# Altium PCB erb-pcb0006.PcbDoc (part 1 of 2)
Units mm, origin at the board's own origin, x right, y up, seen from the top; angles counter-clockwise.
Board outline 100 x 66.5 mm, 4 copper layers (Top Layer, Mid-Layer 1, Mid-Layer 2, Bottom Layer), stack 1.564 mm thick; 134 components, 81 nets, 741 pads, 81 vias.
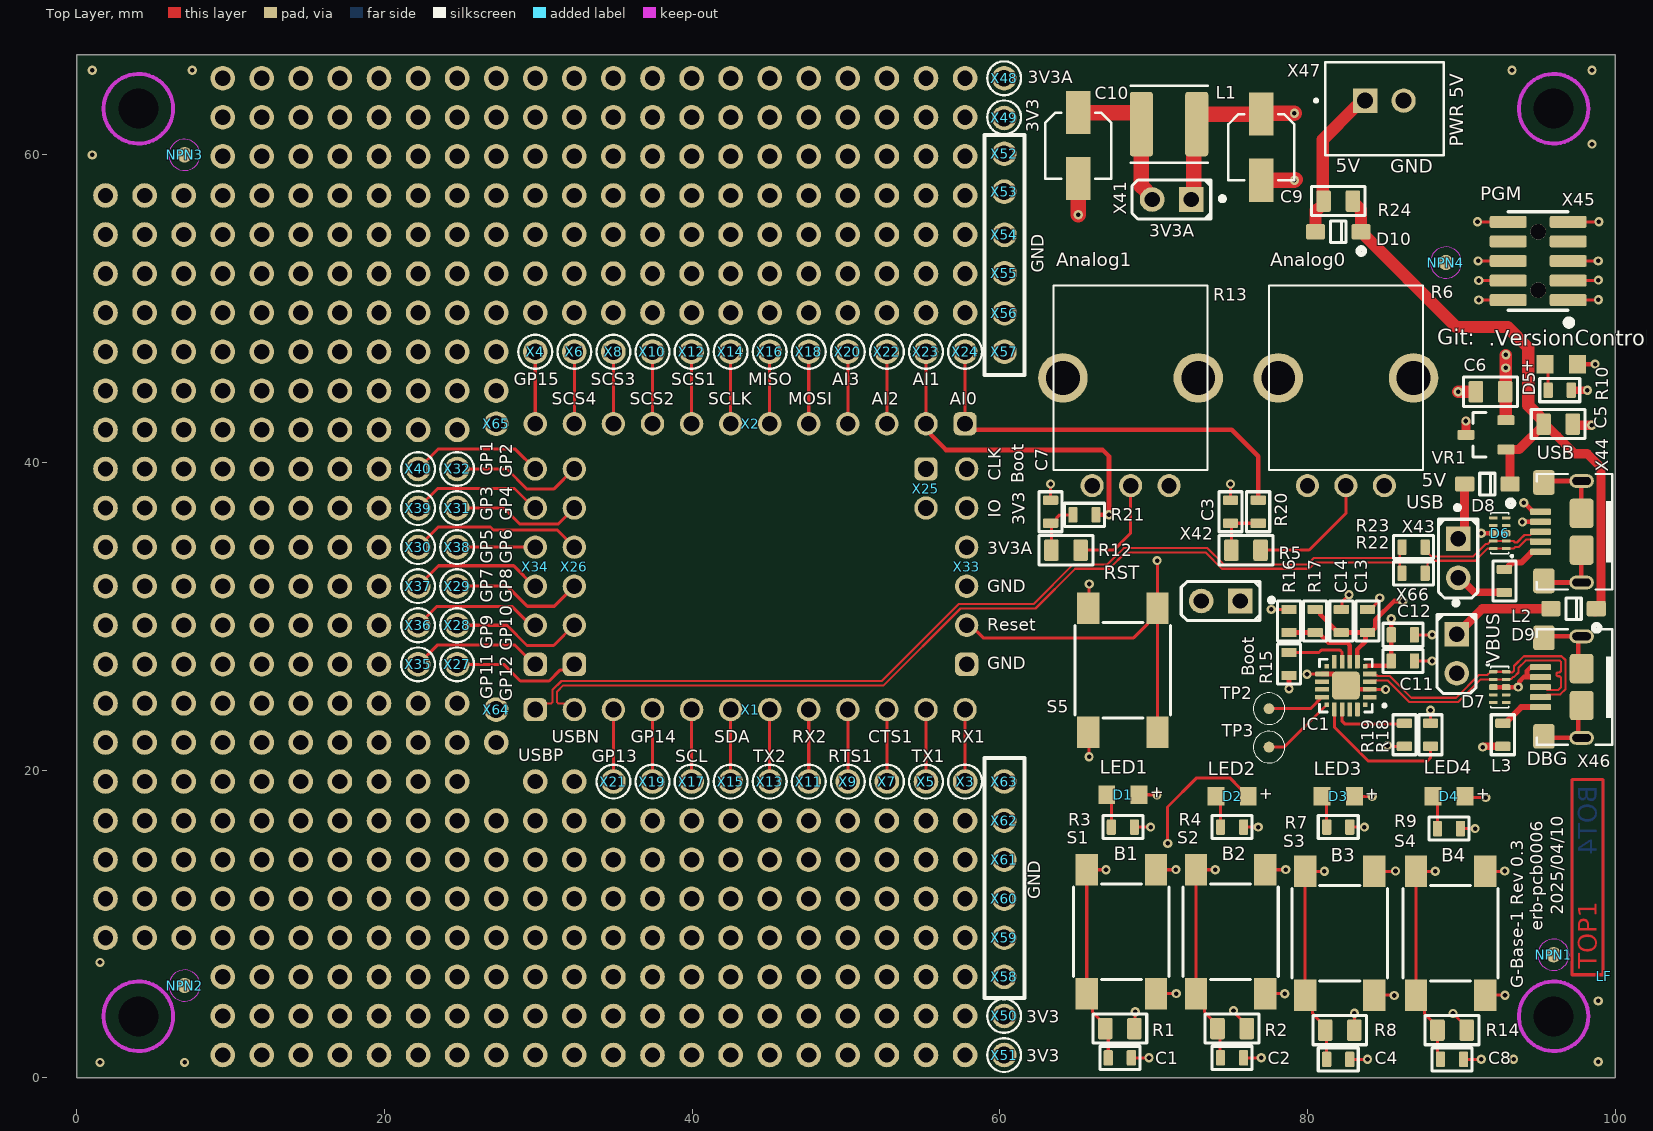
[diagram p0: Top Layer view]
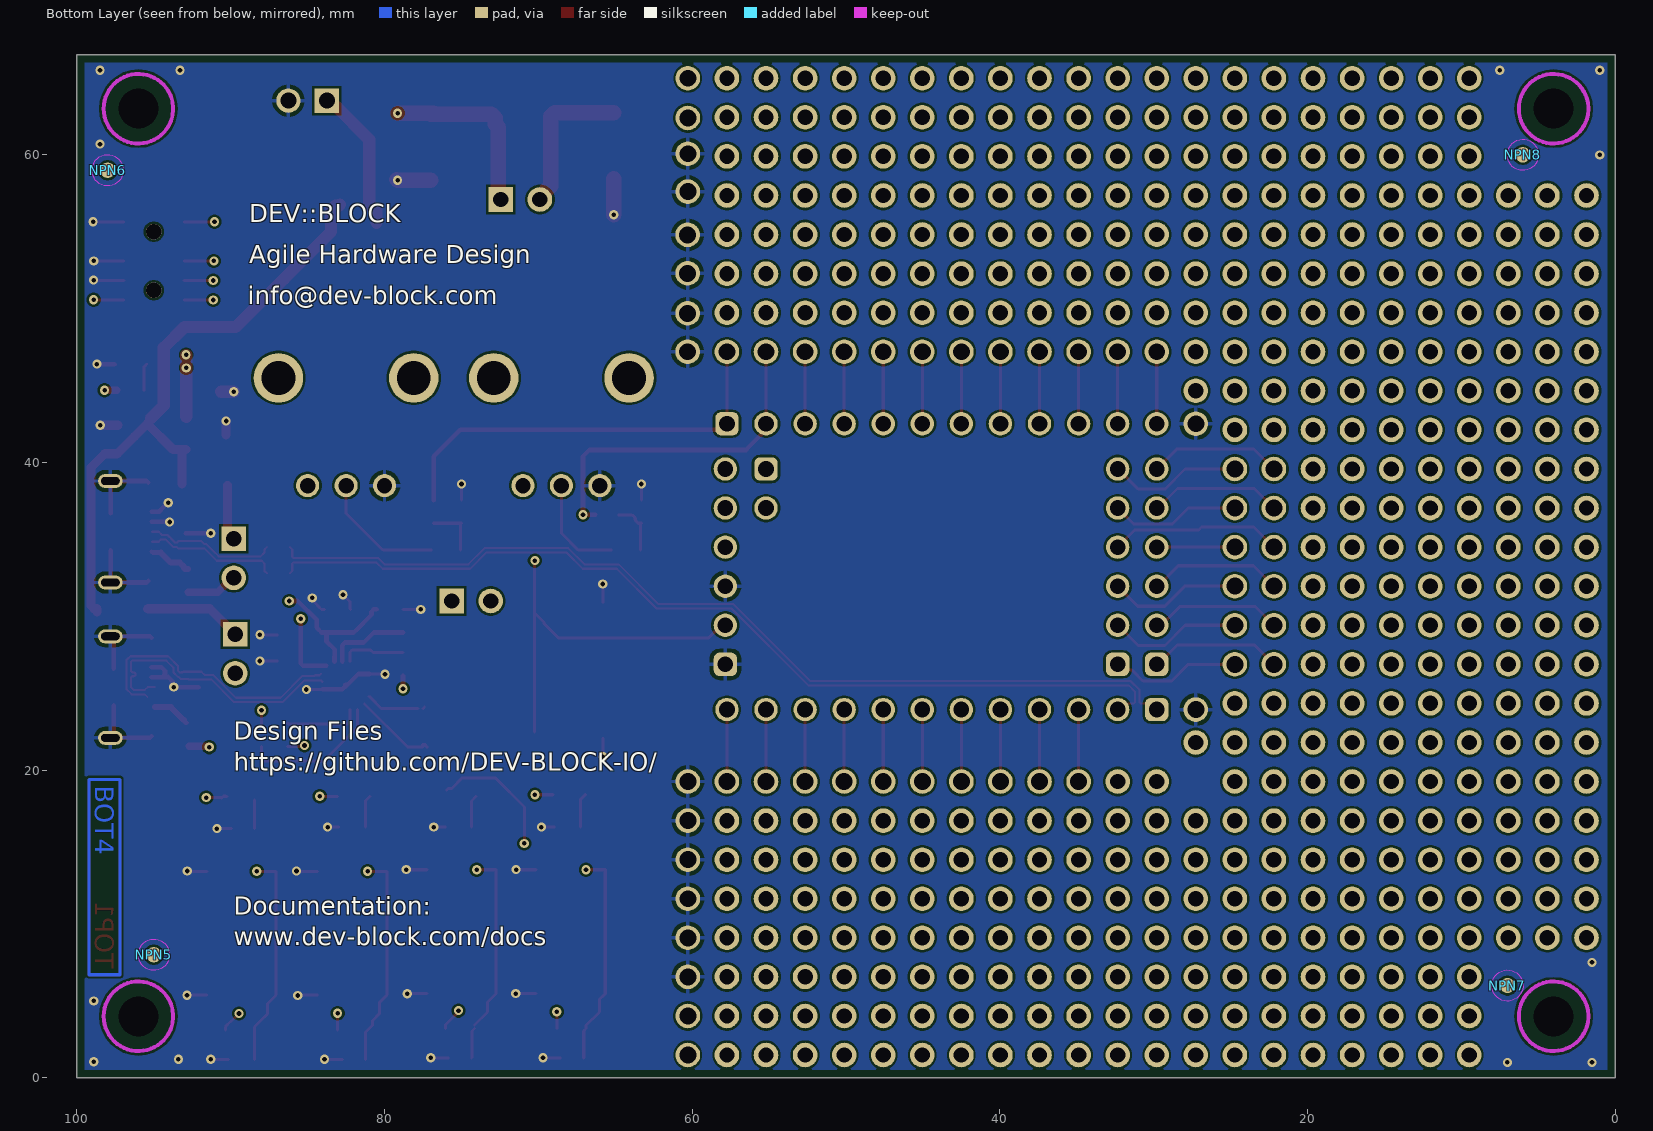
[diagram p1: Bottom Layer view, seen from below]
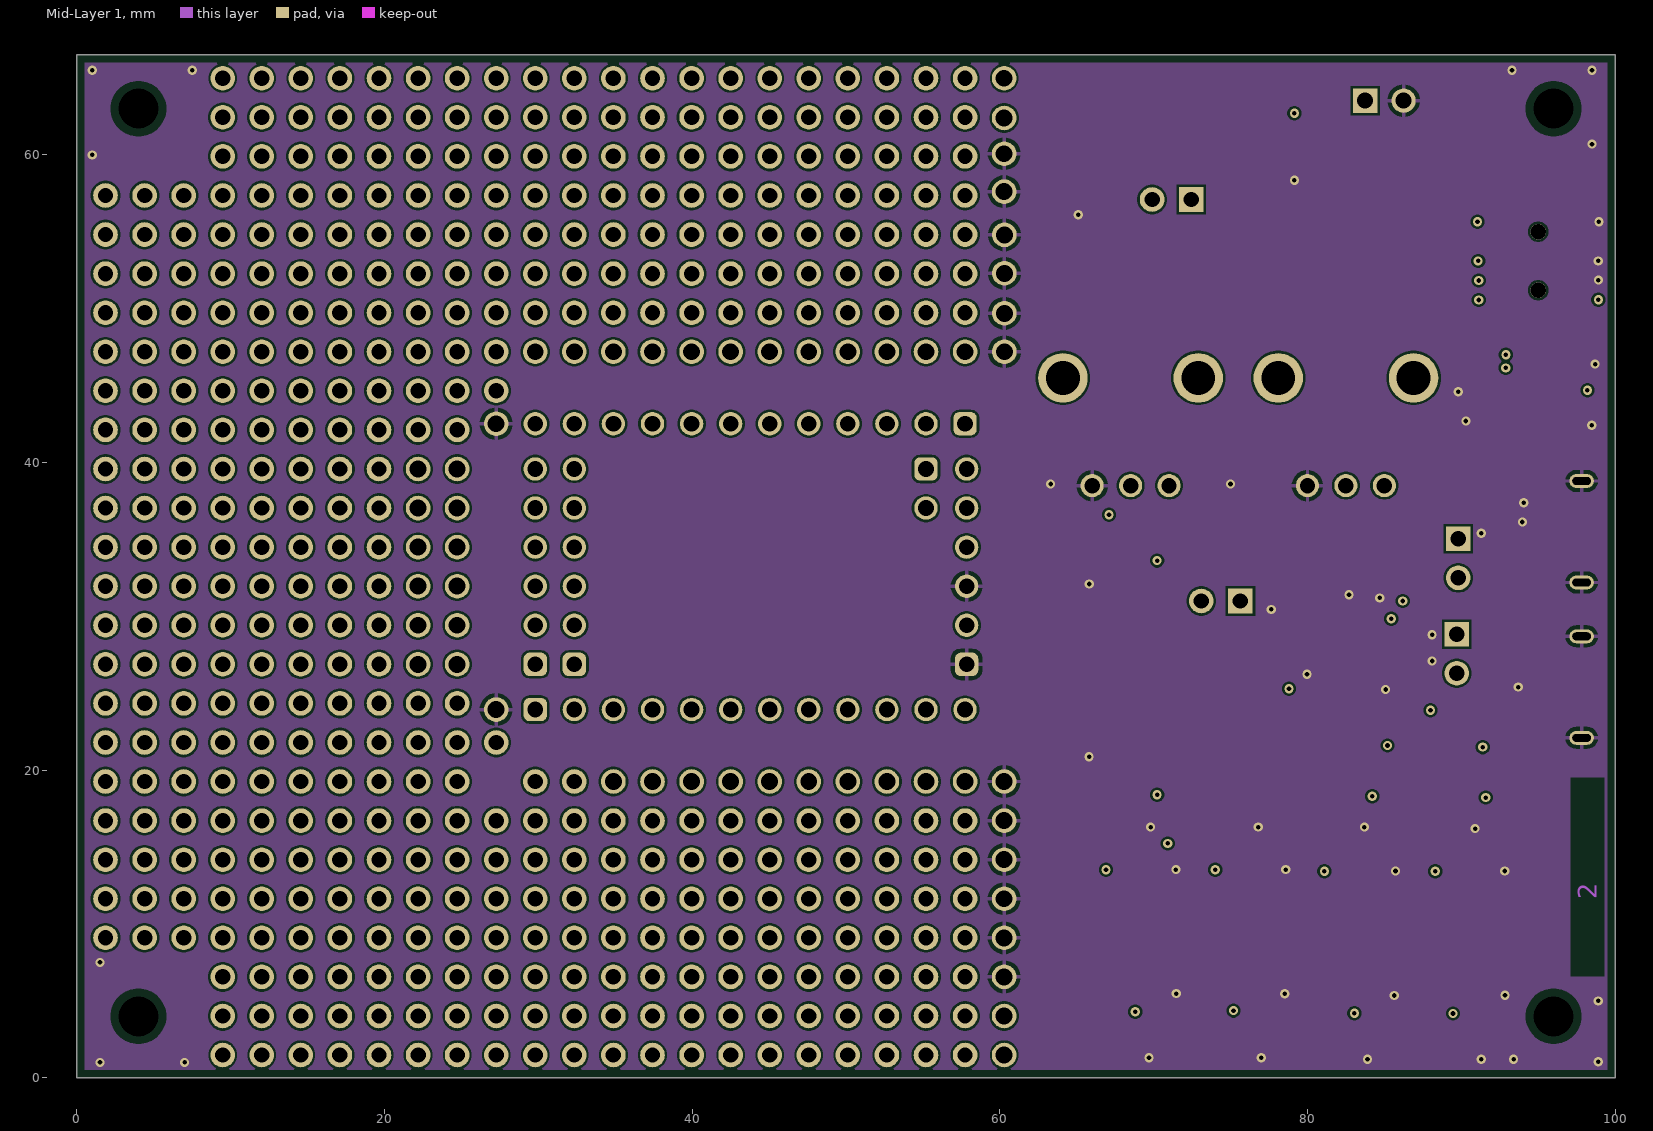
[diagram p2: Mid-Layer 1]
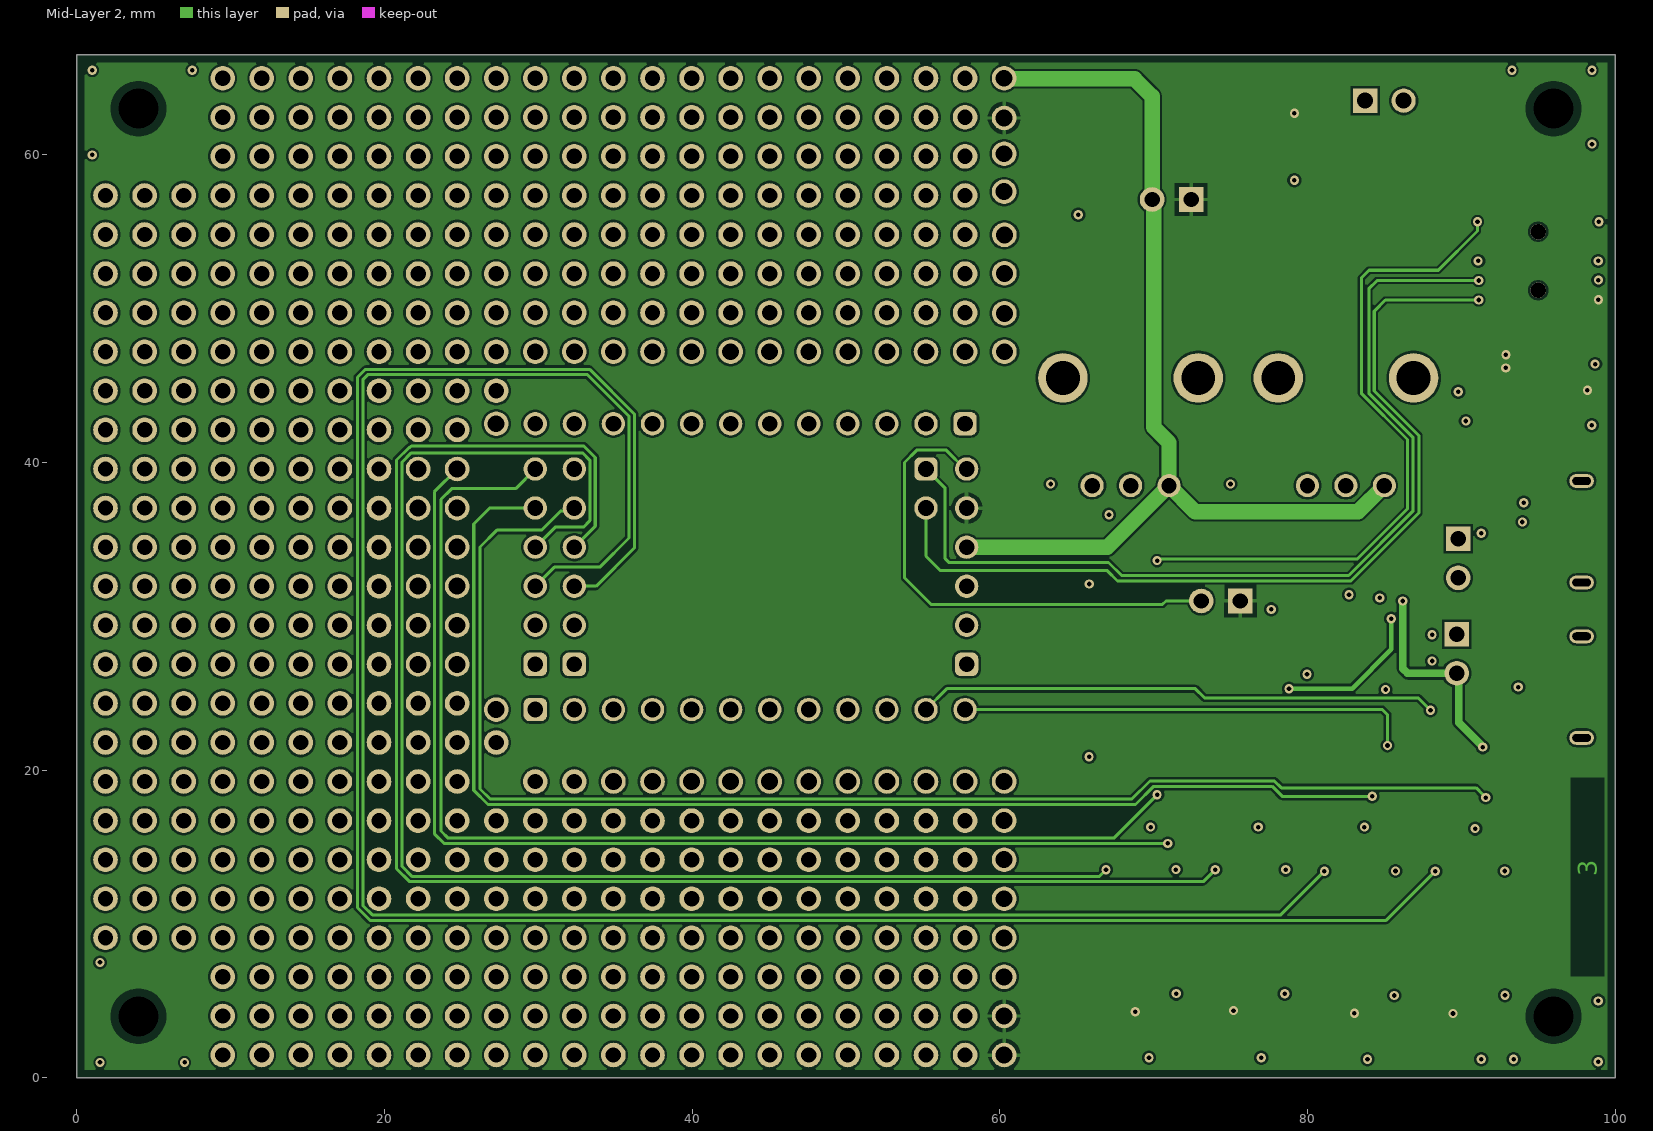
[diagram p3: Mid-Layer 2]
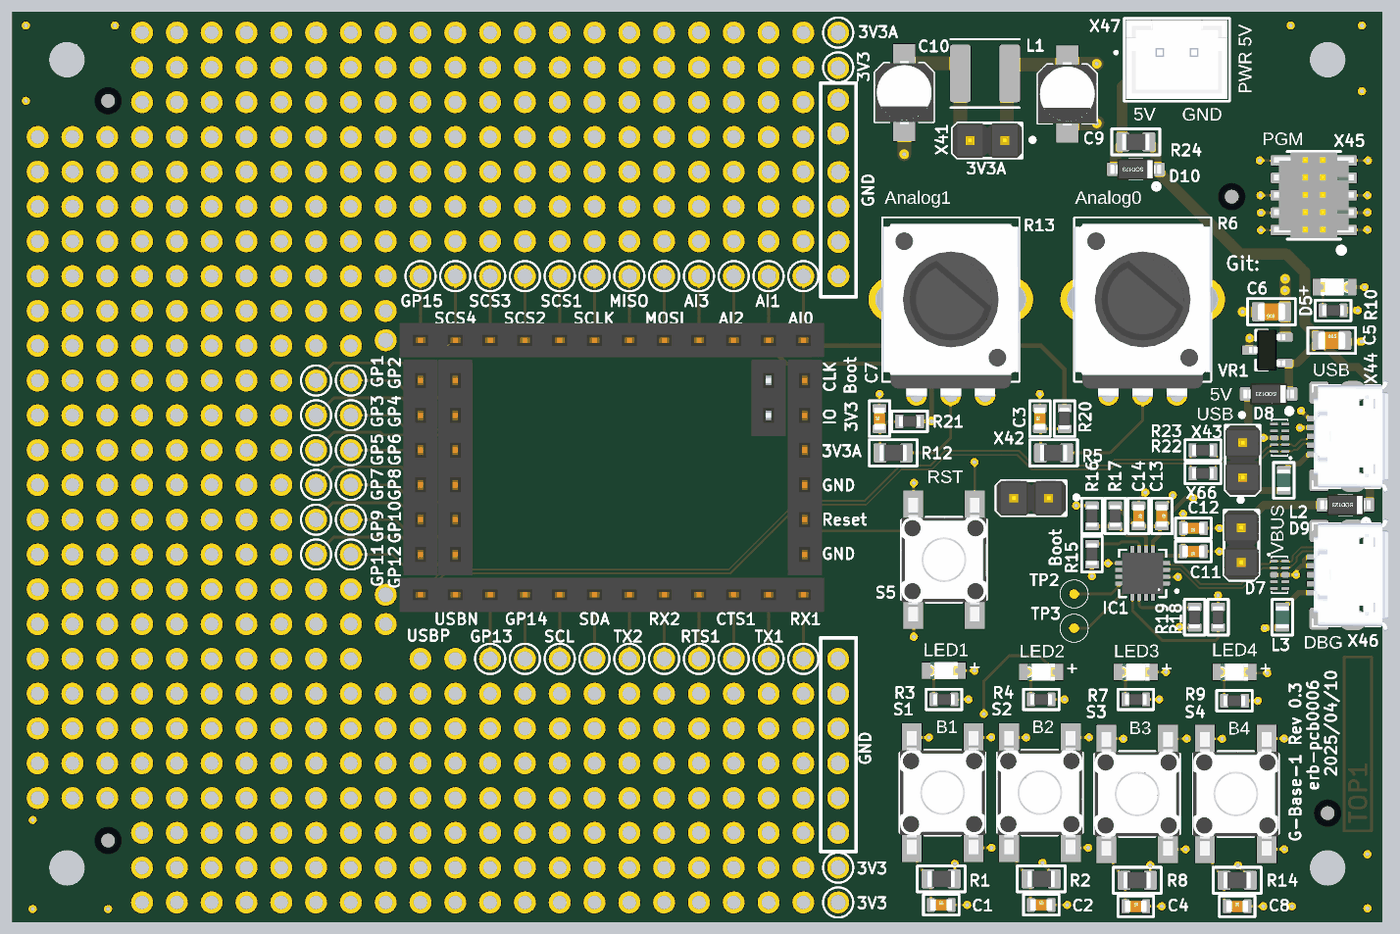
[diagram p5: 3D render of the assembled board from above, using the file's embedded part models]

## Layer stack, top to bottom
Top Solder: solder mask 0.0102, Solder Resist, Dk 3.5
Top Layer: signal copper 0.035
Dielectric 1: dielectric 0.0994, FR-4, Dk 4.8
Mid-Layer 1: signal copper 0.0152
Dielectric3: dielectric 1.265, FR-4, Dk 4.8
Mid-Layer 2: signal copper 0.0152
Dielectric2: dielectric 0.0994, FR-4, Dk 4.8
Bottom Layer: signal copper 0.035
Bottom Solder: solder mask 0.0102, Solder Resist, Dk 3.5

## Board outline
0,0 100,0 100,66.5 0,66.5

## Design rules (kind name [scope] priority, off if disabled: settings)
BoardOutlineClearance BoardOutlineClearance_Text [IsText] p1: gap=0 ignorepadtopadclearanceinfootprint=FALSE
BoardOutlineClearance BoardOutlineClearance_TO [OnLayer('Top Overlay')] p2: gap=0 ignorepadtopadclearanceinfootprint=FALSE
BoardOutlineClearance [All] p3: gap=0.5 ignorepadtopadclearanceinfootprint=FALSE except(0.2: Text-OutlineEdge Text-CavityEdge Text-CutoutEdge Text-SplitBarrior Text-SplitContinuation)
Clearance [HoleDiameter >= 2] p1: gap=0.15 ignorepadtopadclearanceinfootprint=FALSE except(0.5: Arc-Hole Track-Hole SMDPad-Hole THPad-Hole Via-Hole Fill-Hole Poly-Hole Region-Hole Text-Hole)
Clearance Clearance_1 [All] p2: gap=0.15 ignorepadtopadclearanceinfootprint=FALSE
ComponentClearance [All] p1: gap=0 collisioncheckmode=3 verticalgap=0 showdistances=FALSE
DiffPairsRouting [All] p1: maxlimit=0.15 minlimit=0.127 mostfreqgap=0.15 toplayer_mingap=0.15 toplayer_minwidth=0.14 toplayer_maxwidth=0.14 toplayer_prefwidth=0.14 midlayer1_maxgap=0.127 midlayer1_prefgap=0.127 midlayer1_minwidth=0.093 midlayer1_maxwidth=0.093 midlayer1_prefwidth=0.093 midlayer2_maxgap=0.127 midlayer2_prefgap=0.127 midlayer2_minwidth=0.093 midlayer2_maxwidth=0.093 midlayer2_prefwidth=0.093 bottomlayer_mingap=0.15 bottomlayer_minwidth=0.14 bottomlayer_maxwidth=0.14 bottomlayer_prefwidth=0.14 impedanceprofiledriven=TRUE impedanceprofileid={637E84AD-7C76-4CBF-A563-E7FCB9195060} impedanceprofilevalue=90.000000 maxuncoupledlength=12.7
Height [All] p1: minheight=0 maxheight=100 prefheight=12.7
HoleSize [All] p1: absolutevalues=TRUE maxlimit=6 minlimit=0.025 maxpercent=80.000 minpercent=20.000
MinimumSolderMaskSliver [All] p1: minsoldermaskwidth=0.1
PolygonConnect [All] p1: thpad.connectstyle=Relief thpad.reliefconductorwidth=0.254 thpad.reliefentries=4 thpad.polygonreliefangle="90 Angle" thpad.airgapwidth=0.254 smdpad.connectstyle=Relief smdpad.reliefconductorwidth=0.254 smdpad.reliefentries=4 smdpad.polygonreliefangle="90 Angle" smdpad.airgapwidth=0.254 via.connectstyle=Direct via.reliefconductorwidth=0.254 via.reliefentries=4 via.polygonreliefangle="90 Angle" via.airgapwidth=0.254
RoutingVias [All] p1: holewidth=0.3 width=0.6 viastyle="Through Hole" minholewidth=0.3 minwidth=0.6 maxholewidth=0.3 maxwidth=0.6
SilkToSilkClearance [All] p1: silktosilkclearance=0
SilkToSolderMaskClearance [IsPad] p1: minsilkscreentomaskgap=0 clearancetoexposedcopper=TRUE
SolderMaskExpansion [All] p1: expansion=0.05 istentingtop=FALSE
Width [All] p1: maxlimit=1 minlimit=0.14 preferedwidth=0.2 minimp=50.000000 maximp=50.000000 favimp=50.000000
23 further rules are at their usual default settings.

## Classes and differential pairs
net class 90R-DP: DBG_USB_N DBG_USB_P USB_0_D1_N USB_0_D1_P USB_0_D_N USB_0_D_P
differential pair USB_0_D1: +USB_0_D1_P -USB_0_D1_N
differential pair USB_0_D: +USB_0_D_P -USB_0_D_N
differential pair DBG_USB: +DBG_USB_P -DBG_USB_N

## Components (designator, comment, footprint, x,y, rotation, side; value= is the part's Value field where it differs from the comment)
C1 "100n" CAPC1608X95N 67.8,1.3 r0 top value=100nF
C2 "100n" CAPC1608X95N 75.1,1.3 r0 top value=100nF
C3 "100nF" CAPC1608X95N 75,36.8 r90 top
C4 "100n" CAPC1608X95N 82,1.2 r0 top value=100nF
C5 "1uF" CAPC2012X145N 96.3,42.5 r0 top
C6 "10uF" CAPC2012X145N 91.9,44.6 r180 top
C7 "100nF" CAPC1608X95N 63.3,36.8 r90 top
C8 "100n" CAPC1608X95N 89.4,1.2 r0 top value=100nF
C9 "22u" CAPAE4643X54M 77,60.5 r270 top
C10 "22u" CAPAE4643X54M 65.1,60.6 r270 top
C11 "100n" CAPC1608X95N 86.2,27.1 r180 top value=100nF
C12 "4u7" CAPC1608X95N 86.2,28.8 r180 top
C13 "100n" CAPC1608X95N 83.9,29.7 r270 top value=100nF
C14 "4u7" CAPC1608X95N 82.2,29.7 r270 top
D1 "RED" WL-SMCW_0805 68,18.4 r0 top
D2 "RED" WL-SMCW_0805 75.1,18.3 r0 top
D3 "RED" WL-SMCW_0805 82,18.3 r0 top
D4 "RED" WL-SMCW_0805 89.2,18.3 r0 top
D5 "RED" WL-SMCW_0805 96.5,46.4 r180 top
D6 "" "DQA R-PUSON-N10" 92.5,35.4 r90 top
D7 "" "DQA R-PUSON-N10" 92.5,25.4 r270 top
D8 "1N4148W-7-F" SOD-123 91.7,38.6 r180 top
D9 "1N4148W-7-F" SOD-123 97.3,30.5 r180 top
D10 "1N4148W-7-F" SOD-123 82,55 r180 top
IC1 "CP2102N-A02" SILABS_CP2102N-A02-GQFN20R 82.5,25.5 r180 top
L1 "2u2" INDP5050X39N 71,62 r180 top
L2 "120R" INDC1608X95AN 92.8,32.3 r90 top
L3 "120R" INDC1608X95AN 92.7,22.3 r90 top
LF "" LAGENKENNER_4MLL 99.3,6.6 r90 top
NPN1 "FID" Fiducial_1mm 96,8 r90 top
NPN2 "FID" Fiducial_1mm 7,6 r90 top
NPN3 "FID" Fiducial_1mm 7,60 r90 top
NPN4 "FID" Fiducial_1mm 89,53 r90 top
NPN5 "FID" Fiducial_1mm 95,8 r90 bottom
NPN6 "FID" Fiducial_1mm 98,59 r90 bottom
NPN7 "FID" Fiducial_1mm 7,6 r90 bottom
NPN8 "FID" Fiducial_1mm 6,60 r90 bottom
R1 "100k" RESC2012X70N 67.8,3.2 r0 top
R2 "100k" RESC2012X70N 75.1,3.2 r0 top
R3 "560R" RESC1608X55N 68,16.3 r180 top
R4 "560R" RESC1608X55N 75.1,16.3 r180 top
R5 "100k" RESC2012X70N 76,34.3 r0 top
R6 "POT_50k_lin_9mm" PTV09 82.5,45.5 r0 top locked
R7 "560R" RESC1608X55N 82,16.3 r180 top
R8 "100k" RESC2012X70N 82.1,3.1 r0 top
R9 "560R" RESC1608X55N 89.2,16.2 r180 top
R10 "560R" RESC1608X55N 96.4,44.7 r180 top
R12 "100k" RESC2012X70N 64.3,34.3 r0 top
R13 "POT_50k_lin_9mm" PTV09 68.5,45.5 r0 top locked
R14 "100k" RESC2012X70N 89.4,3.1 r0 top
R15 "1k" RESC1608X55AN 78.8,26.9 r90 top
R16 "33k" RESC1608X55AN 78.8,29.7 r90 top
R17 "22k" RESC1608X55AN 80.5,29.7 r270 top
R18 "0R" RESC1608X55N 88,22.3 r90 top
R19 "0R" RESC1608X55N 86.3,22.3 r270 top
R20 "0R" RESC1608X55N 76.8,36.8 r90 top
R21 "0R" RESC1608X55N 65.5,36.6 r0 top
R22 "0R" RESC1608X55N 86.9,32.8 r180 top
R23 "0R" RESC1608X55N 86.9,34.5 r180 top
R24 "DNP" RESC2012X70N 82,57 r180 top
S1 "UK-B0228-G5-160-JZ" UK-B0228-G5-160-JZ 67.9,9.5 r90 top locked
S2 "UK-B0228-G5-160-JZ" UK-B0228-G5-160-JZ 75,9.5 r90 top locked
S3 "UK-B0228-G5-160-JZ" UK-B0228-G5-160-JZ 82.1,9.4 r90 top locked
S4 "UK-B0228-G5-160-JZ" UK-B0228-G5-160-JZ 89.3,9.4 r90 top locked
S5 "UK-B0228-G5-160-JZ" UK-B0228-G5-160-JZ 68,26.5 r270 top
TP2 "TP 0.7mm" TP_0.7mm 77.5,24 r90 top
TP3 "TP 0.7mm" TP_0.7mm 77.5,21.5 r90 top
VR1 "AP7375-33SA-7" SOT95P280X135-3N_123 91.6,41.8 r180 top
X1 "HDR 1x12" 61301211821_NO 43.77,23.94 r0 top locked
X2 "HDR 1x12" 61301211821_NO 43.77,42.52 r180 top
X3 "PAD" PAD_1.1_1.6#1 57.74,19.26 r0 top net-tie
X4 "PAD" PAD_1.1_1.6#1 29.8,47.2 r0 top net-tie
X5 "PAD" PAD_1.1_1.6#1 55.2,19.26 r0 top net-tie
X6 "PAD" PAD_1.1_1.6#1 32.34,47.2 r0 top net-tie
X7 "PAD" PAD_1.1_1.6#1 52.66,19.26 r0 top net-tie
X8 "PAD" PAD_1.1_1.6#1 34.88,47.2 r0 top net-tie
X9 "PAD" PAD_1.1_1.6#1 50.12,19.26 r0 top net-tie
X10 "PAD" PAD_1.1_1.6#1 37.42,47.2 r0 top net-tie
X11 "PAD" PAD_1.1_1.6#1 47.58,19.26 r0 top net-tie
X12 "PAD" PAD_1.1_1.6#1 39.96,47.2 r90 top net-tie
X13 "PAD" PAD_1.1_1.6#1 45.04,19.26 r0 top net-tie
X14 "PAD" PAD_1.1_1.6#1 42.5,47.2 r90 top net-tie
X15 "PAD" PAD_1.1_1.6#1 42.5,19.26 r90 top net-tie
X16 "PAD" PAD_1.1_1.6#1 45.04,47.2 r90 top net-tie
X17 "PAD" PAD_1.1_1.6#1 39.96,19.26 r90 top net-tie
X18 "PAD" PAD_1.1_1.6#1 47.58,47.2 r90 top net-tie
X19 "PAD" PAD_1.1_1.6#1 37.42,19.26 r90 top net-tie
X20 "PAD" PAD_1.1_1.6#1 50.12,47.2 r90 top net-tie
X21 "PAD" PAD_1.1_1.6#1 34.88,19.26 r90 top net-tie
X22 "PAD" PAD_1.1_1.6#1 52.66,47.2 r90 top net-tie
X23 "PAD" PAD_1.1_1.6#1 55.2,47.2 r90 top net-tie
X24 "PAD" PAD_1.1_1.6#1 57.74,47.2 r90 top net-tie
X25 "HDR 1x2" 61300211821_NO 55.2,38.31 r270 top
X26 "HDR 1x6" 61300611821_NO 32.34,33.23 r90 top
X27 "PAD" PAD_1.1_1.6#1 24.72,26.88 r90 top net-tie
X28 "PAD" PAD_1.1_1.6#1 24.72,29.42 r90 top net-tie
X29 "PAD" PAD_1.1_1.6#1 24.72,31.96 r90 top net-tie
X30 "PAD" PAD_1.1_1.6#1 22.18,34.5 r90 top net-tie
X31 "PAD" PAD_1.1_1.6#1 24.72,37.04 r90 top net-tie
X32 "PAD" PAD_1.1_1.6#1 24.72,39.58 r90 top net-tie
X33 "HDR 1x6" 61300611821_NO 57.84,33.23 r90 top
X34 "HDR 1x6" 61300611821_NO 29.8,33.23 r90 top
X35 "PAD" PAD_1.1_1.6#1 22.18,26.88 r0 top net-tie
X36 "PAD" PAD_1.1_1.6#1 22.18,29.42 r90 top net-tie
X37 "PAD" PAD_1.1_1.6#1 22.18,31.96 r90 top net-tie
X38 "PAD" PAD_1.1_1.6#1 24.72,34.5 r90 top net-tie
X39 "PAD" PAD_1.1_1.6#1 22.18,37.04 r90 top net-tie
X40 "PAD" PAD_1.1_1.6#1 22.18,39.58 r90 top net-tie
X41 "HDR 1x2" CON_HEADER2.54_1X2W 69.9,57.1 r270 top
X42 "HDR 1x2" CON_HEADER2.54_1X2W 73.1,31 r270 top
X43 "HDR 1x2" CON_HEADER2.54_1X2W 89.8,32.5 r0 top
X44 "10118193-0001LF" USB-MICRO-B-RA-SMD-PIP 95.4,35.5 r180 top locked
X45 "FTSH-107-01-L-DV-K" HDR_2X5-SMD-1.27MM-K 95,53.1 r90 top locked value="Pin Header 2x5, 1.27mm"
X46 "10118193-0001LF" USB-MICRO-B-RA-SMD-PIP 95.4,25.4 r180 top locked
X47 "B2B-XH" JST_B2B-XH-A_(LF)(SN) 85,63 r180 top
X48 "PAD" PAD_1.1_1.6#2 60.28,65.054 r90 top net-tie
X49 "PAD" PAD_1.1_1.6#3 60.3,62.4 r90 top net-tie
X50 "PAD" PAD_1.1_1.6#4 60.228,4.006 r90 top net-tie
X51 "PAD" PAD_1.1_1.6#5 60.228,1.449 r0 top net-tie
X52 "PAD" PAD_1.1_1.6#1 60.28,60.075 r90 top net-tie
X53 "PAD" PAD_1.1_1.6#1 60.28,57.61 r90 top net-tie
X54 "PAD" PAD_1.1_1.6#1 60.3,54.8 r90 top net-tie
X55 "PAD" PAD_1.1_1.6#1 60.3,52.3 r90 top net-tie
X56 "PAD" PAD_1.1_1.6#1 60.3,49.7 r90 top net-tie
X57 "PAD" PAD_1.1_1.6#1 60.3,47.2 r90 top net-tie
X58 "PAD" PAD_1.1_1.6#6 60.228,6.631 r90 top net-tie
X59 "PAD" PAD_1.1_1.6#7 60.374,9.149 r90 top net-tie
X60 "PAD" PAD_1.1_1.6#8 60.374,11.438 r90 top net-tie
X61 "PAD" PAD_1.1_1.6#9 60.374,14.054 r0 top net-tie
X62 "PAD" PAD_1.1_1.6#10 60.374,16.736 r90 top net-tie
X63 "PAD" PAD_1.1_1.6#11 60.228,19.26 r90 top net-tie
X64 "PAD" PAD_1.1_1.6#12 27.25,23.875 r90 top net-tie
X65 "PAD" PAD_1.1_1.6#13 27.275,42.475 r90 top net-tie
X66 "HDR 1x2" CON_HEADER2.54_1x2W 89.7,26.3 r0 top

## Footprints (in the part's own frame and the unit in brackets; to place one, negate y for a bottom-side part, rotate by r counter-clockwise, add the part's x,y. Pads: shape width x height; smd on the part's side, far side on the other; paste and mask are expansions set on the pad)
61300211821_NO [mm] "Socket Header, Pitch 2.54 mm, THT, Vertical, single row, 2p"
  rrect50% 1.52x1.52 hole 1.02: 1(-1.27,0)
  round 1.52 hole 1.02: 2(1.27,0)
  body extent -2.79,-1.25 2.79,1.25, height 8.55
61300611821_NO [mm] "Socket Header, Pitch 2.54 mm, THT, Vertical, single row, 6p"
  rrect50% 1.52x1.52 hole 1.02: 1(-6.35,0)
  round 1.52 hole 1.02: 2(-3.81,0) 3(-1.27,0) 4(1.27,0) 5(3.81,0) 6(6.35,0)
  body extent -7.87,-1.25 7.87,1.25, height 8.55
61301211821_NO [mm] "Socket Header, Pitch 2.54 mm, THT, Vertical, single row, 12p"
  rrect50% 1.52x1.52 hole 1.02: 1(-13.97,0)
  round 1.52 hole 1.02: 2(-11.43,0) 3(-8.89,0) 4(-6.35,0) 5(-3.81,0) 6(-1.27,0) 7(1.27,0) 8(3.81,0) 9(6.35,0) 10(8.89,0) 11(11.43,0) 12(13.97,0)
  body extent -15.49,-1.25 15.49,1.25, height 8.55
CAPAE4643X54M [mm] "Aluminum Electrolytic Capacitor, Body 4,30x4,30x5,40mm, IPC Low Density"
  rect 2.8x1.6 smd: 1(-2.15,0) 2(2.15,0)
  silkscreen extent -2.15,-2.15 2.15,2.15, body extent -2.3,-2.15 2.3,2.15, height 5.4
CAPC1608X95N [mm] "Chip Capacitor, 2-Leads, Body 1,6x0,8mm, imperial 0603"
  rrect25% 0.6x1 smd: 1(-0.75,0) 2(0.75,0)
  silkscreen extent -1.3,-0.75 1.3,0.75, body extent -0.8,-0.4 0.8,0.4, height 0.3
CAPC2012X145N [mm] "Chip Capacitor, 2-Leads, Body 2,0x1,25mm, imperial 0805"
  rrect25% 0.95x1.4 smd: 1(-0.95,0) 2(0.95,0)
  silkscreen extent -1.75,-0.95 1.75,0.95, body extent -1,-0.62 1,0.63, height 0.78
CON_HEADER2.54_1X2W [mm]
  rect 1.6x1.6 hole 1: 1(0,2.54)
  round 1.6 hole 1: 2(0,0)
  silkscreen extent -1.27,-1.31 1.27,4.71, body extent -1.27,-1.27 1.27,3.81, height 9.51
CON_HEADER2.54_1x2W [mm]
  rect 1.6x1.6 hole 1: 1(0,2.54)
  round 1.6 hole 1: 2(0,0)
  silkscreen extent -1.27,-1.31 1.27,4.71, body extent -1.27,-1.27 1.27,3.81, height 9.51
"DQA R-PUSON-N10" [mm]
  rrect50% 0.2x0.56 smd mask+0.05: 1(-1,-0.415) 2(-0.5,-0.415) 4(0.5,-0.415) 5(1,-0.415) 6(1,0.415) 7(0.5,0.415) 9(-0.5,0.415) 10(-1,0.415)
  rrect50% 0.4x0.56 smd mask+0.05: 3(0,-0.415) 8(0,0.415)
  silkscreen extent -1.5,-0.81 1.34,0.59, body extent -1.25,-0.5 1.25,0.5, height 0.55
Fiducial_1mm [mm]
  round 1 smd mask+0.5: 0(0,0)
  Top Layer keep-out circle w0.01: c0,0 r1.016
HDR_2X5-SMD-1.27MM-K [mm]
  rrect25% 0.76x2.4 smd: 1(-2.54,-1.95) 2(-2.54,1.95) 3(-1.27,-1.95) 4(-1.27,1.95) 5(0,-1.95) 6(0,1.95) 7(1.27,-1.95) 8(1.27,1.95) 9(2.54,-1.95) 10(2.54,1.95)
  round 1.02 hole 1.02: ""(-1.905,0) ""(1.905,0)
  silkscreen extent -4.21,-2.21 3.2,1.95, body extent -3.14,-2.92 3.14,2.92, height 6.11
INDC1608X95AN [mm] "Chip Inductor, 2-Leads, Body 1,6x0,8mm, imperial 0603"
  rrect25% 0.6x1 smd: 1(-0.75,0) 2(0.75,0)
  silkscreen extent -1.3,-0.75 1.3,0.75, body extent -0.8,-0.47 0.8,0.48, height 0.8
INDP5050X39N [mm] "Precision Wire Wound Inductor, 2-Leads, Body 4,95x4,95mm, IPC Medium Density"
  rrect25% 1.5x4.2 smd: 1(-1.8,0) 2(1.8,0)
  silkscreen extent -2.5,-2.5 2.5,2.5, body extent -2.47,-2.47 2.48,2.48, height 3.9
JST_B2B-XH-A_(LF)(SN) [mm]
  rect 1.575x1.575 hole 1.05: 1(1.25,-0.525)
  round 1.575 hole 1.05: 2(-1.25,-0.525)
  silkscreen extent -3.85,-3.03 4.54,3.03, body extent -3.7,-2.88 3.7,2.88, height 7
LAGENKENNER_4MLL [mm] "Pin Header, pitch 2.54 mm, THT, Vertical, single row, 2p"
  Top Layer lines w0.2: 0.1,2.1 12.8,2.1 12.8,0.1 0.1,0.1 0.1,2.1
  Bottom Layer lines w0.2: 0.1,2.1 12.8,2.1 12.8,0.1 0.1,0.1 0.1,2.1
  Multi-Layer pour cut-out: 0,2.2 0,0 12.9,0 12.9,2.2
PAD_1.1_1.6#1 [mm]
  round 1.6 hole 1.1: 1(0,0)
PAD_1.1_1.6#2 [mm]
  round 1.6 hole 1.1: 1(-0.074,0)
PAD_1.1_1.6#3 [mm]
  round 1.6 hole 1.1: 1(0,0.02)
PAD_1.1_1.6#4 [mm]
  round 1.6 hole 1.1: 1(0.014,-0.052)
PAD_1.1_1.6#5 [mm]
  round 1.6 hole 1.1: 1(0.052,0.031)
PAD_1.1_1.6#6 [mm]
  round 1.6 hole 1.1: 1(-0.071,-0.052)
PAD_1.1_1.6#7 [mm]
  round 1.6 hole 1.1: 1(-0.049,0.094)
PAD_1.1_1.6#8 [mm]
  round 1.6 hole 1.1: 1(0.202,0.094)
PAD_1.1_1.6#9 [mm]
  round 1.6 hole 1.1: 1(-0.094,0.126)
PAD_1.1_1.6#10 [mm]
  round 1.6 hole 1.1: 1(-0.016,0.094)
PAD_1.1_1.6#11 [mm]
  round 1.6 hole 1.1: 1(0,-0.052)
PAD_1.1_1.6#12 [mm]
  round 1.6 hole 1.1: 1(0.065,-0.01)
PAD_1.1_1.6#13 [mm]
  round 1.6 hole 1.1: 1(0.045,0.015)
PTV09 [mm]
  round 1.508 hole 1: 1(-2.5,-7) 2(0,-7) 3(2.5,-7)
  round 3.216 hole 2.2: NC1(-4.4,0) NC2(4.4,0)
  silkscreen extent -5,-6 5,6, body extent -5.69,-7.1 5.7,5.5, height 25.5
RESC1608X55AN [mm] "Chip Resistor, 2-Leads, Body 1,6x0,85mm, imperial 0603"
  rrect25% 0.6x1 smd: 1(-0.75,0) 2(0.75,0)
  silkscreen extent -1.3,-0.75 1.3,0.75, body extent -0.8,-0.4 0.8,0.4, height 0.55
RESC1608X55N [mm]
  rrect25% 0.6x1 smd: 1(-0.75,0) 2(0.75,0)
  silkscreen extent -1.3,-0.75 1.3,0.75, body extent -0.8,-0.4 0.8,0.4, height 0.55
RESC2012X70N [mm] "Chip Resistor, 2-Leads, Body 2,0x1,25mm, imperial 0805"
  rrect25% 0.95x1.4 smd: 1(-0.95,0) 2(0.95,0)
  silkscreen extent -1.75,-0.95 1.75,0.95, body extent -1,-0.6 1,0.6, height 0.7
SILABS_CP2102N-A02-GQFN20R [mm]
  rrect25% 0.3x0.3 smd mask+0.05: 1(-1.25,1.25) 6(-1.25,-1.25) 11(1.25,-1.25) 16(1.25,1.25)
  rrect25% 0.9x0.3 smd mask+0.05: 2(-1.55,0.75) 3(-1.55,0.25) 4(-1.55,-0.25) 5(-1.55,-0.75) 12(1.55,-0.75) 13(1.55,-0.25) 14(1.55,0.25) 15(1.55,0.75)
  rrect25% 0.3x0.9 smd mask+0.05: 7(-0.75,-1.55) 8(-0.25,-1.55) 9(0.25,-1.55) 10(0.75,-1.55) 17(0.75,1.55) 18(0.25,1.55) 19(-0.25,1.55) 20(-0.75,1.55)
  rrect25% 1.8x1.8 smd: 21(0,0)
  silkscreen extent -2.6,-1.72 1.72,1.72, body extent -1.5,-1.5 1.5,1.5, height 0.8
SOD-123 [mm]
  rrect25% 1.25x1 smd: 1(1.475,0) 2(-1.475,0)
  silkscreen extent -1.7,-0.7 0.5,1.45, body extent -1.85,-0.77 1.85,0.78, height 1.35
SOT95P280X135-3N_123 [mm] "SOT23, 3-Leads, Body 3,0x3,0mm (max), Pitch 0,95mm, IPC Medium Density"
  rrect25% 1.1x0.65 smd: 1(-1.3,0.95) 2(-1.3,-0.95) 3(1.3,0)
  silkscreen extent 0,-1.45 0.85,1.45, body extent -1.3,-1.5 1.34,1.5, height 1.08
TP_0.7mm [mm]
  round 0.7 smd paste-10: 1(0,0)
  silkscreen extent -1.02,-1.02 1.02,1.02, body extent -0.4,-0.4 0.4,0.4, height 0.01
UK-B0228-G5-160-JZ [mm] "SMD Tact Switch, body 6x6mm"
  rect 2.05x1.45 smd: 1(-4.025,2.25) 2(4.025,2.25) 3(-4.025,-2.25) 4(4.025,-2.25)
  silkscreen extent -3.1,-3.1 3.1,3.1, body extent -4.5,-3.1 4.5,3.1, height 7
USB-MICRO-B-RA-SMD-PIP [mm]
  rrect25% 1.35x0.4 smd: 1(0.25,1.3) 2(0.25,0.65) 3(0.25,0) 4(0.25,-0.65) 5(0.25,-1.3)
  oval 1.6x0.9 hole 0.5 slot 1.2 at 0 deg: 6(-2.425,3.3) 6(-2.425,-3.3)
  oval 2x1.5 on Top Paste: 6(-2.425,3.3) 6(-2.425,-3.3)
  rrect25% 1.55x1.9 smd: 6(-2.425,-1.2) 6(-2.425,1.2)
  rrect25% 1.4x1.6 smd: 6(0.025,3.2) 6(0.025,-3.2)
  silkscreen extent -4.5,-3.75 0.5,3.75, body extent -5.03,-4.1 0.4,4.1, height 2.72
WL-SMCW_0805 [mm] "SMD Mono-color Chip LED, body 2.0x1.25mm"
  rect 1.1x1.2 smd: A(1.05,0) K(-1.05,0)
  body extent -1,-0.63 1,0.62, height 0.7

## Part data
C1 C2 C4 C8 C11 C13: library part C_100n_50V_0603, "100n_50V", JLC=C14663, Manufacturer=AVX, Manufacturer Part Number=06031C104KAT2A, Tolerance=+-10%, Voltage Rating=50V
C3 C7: library part CAP_100nF_0603, "Multilayer Ceramic Capacitors MLCC - SMD/SMT, 100nF", JLC=C14663, Manufacturer=YAGEO, Manufacturer Part Number=CC0603KRX7R9BB104, Tolerance=10%, Voltage Rating=50VDC
C5: library part CAP_1uF_0805, "Multilayer Ceramic Capacitors MLCC - SMD/SMT, 1uF", JLC=C28323, Manufacturer="Samsung Electro-Mechanics", Manufacturer Part Number=CL21B105KBFNNNE, Tolerance=10%, Voltage Rating=50V
C6: library part CAP_10uF_0805, "Multilayer Ceramic Capacitors MLCC - SMD/SMT, 10uF", JLC=C15850, Manufacturer="Samsung Electro-Mechanics", Manufacturer Part Number=CL21A106KAYNNNE, Tolerance=10%, Voltage Rating=25V
C9 C10: library part CAP_22u, "Aluminium Electrolytic Capacitors - SMD 22UF 16V HA SMD", Manufacturer=Panasonic, Manufacturer Part Number=EEE-HAC220WAR, Tolerance=20%, Voltage Rating=16V
C12 C14: library part CAP_4u7_0603, "16V 4.7uF X5R ±10% 0603 Multilayer Ceramic Capacitors MLCC - SMD/SMT ROHS", JLC=C19666, Manufacturer="Murata Electronics", Manufacturer Part Number=GRM188C81C475KE11D, Tolerance=10%, Voltage Rating=16VDC
D1 D2 D3 D4 D5: library part LED_0805_RED_AK, "Standard LEDs - SMD WL-SMCW SMDMono TpVw Waterclr 0805 Red", JLC=C84256, Manufacturer="Wurth Elektronik", Manufacturer Part Number=150080RS75000, Voltage Rating=2.0
D6 D7: library part TPD4EUSB30DQAR, "2-, 4-Channel ESD Protection for Super-Speed USB 3.0 Interface", Manufacturer="Texas Instruments"
D8 D9 D10: "Diodes - General Purpose, Power, Switching SURFACE MOUNT FAST SWITCHING DIODE 2A", JLC=C81598, Manufacturer="Diodes Incorporated", Package=SOD-123
IC1: library part IC_CP2102N-A02-QFN20, "USB Interface IC USBXpress - USB to UART Bridge QFN28", JLC=C969913, Manufacturer="Silicon Labs", Manufacturer Part Number=CP2102N-A02-GQFN20R
L1: library part IND_2u2_3.8A, "Fixed Inductors 2.2uH 3.8A", JLC=N/A, Manufacturer=Bourns, Manufacturer Part Number=SRN5040TA-2R2M, Tolerance=10%, Voltage Rating=50V
L2 L3: library part FB_600R_0603, "Chip Bead Inductors for Power Lines", Manufacturer="Taiyo Yuden", Manufacturer Part Number=FBMH1608HL121-T
NPN1 NPN2 NPN3 NPN4 NPN5 NPN6 NPN7 NPN8: library part Fiducial_1mm
R1 R2 R5 R8 R12 R14: library part RES_100k_0805, "Thick Film Resistors - SMD 1/8watt 100Kohms 1% 100ppm", JLC=C17407, Manufacturer="Vishay / Dale", Manufacturer Part Number=CRCW0805100KFKEA, Tolerance=1%, Voltage Rating=150V
R3 R4 R7 R9 R10: library part RES_560R_0603, "Thick Film Resistors - SMD 560 Ohms 125 mW 0603", JLC=C224731, Manufacturer="ROHM Semicon", Manufacturer Part Number=MCR03ERTF5600, Tolerance=1%, Voltage Rating=150V
R6 R13: "PTV09A-4020F-A203 50k, 20mm", Manufacturer=Bourns, Manufacturer Part Number=PTV09A-5020F-A503, Tolerance=20%
R15: library part RES_1k_0603, "Thick Film Resistors - SMD 1 kOhms 100mW 0603 1%", JLC=C21190, Manufacturer=Yageo, Manufacturer Part Number=RC0603FR-071KL, Tolerance=1%, Voltage Rating=75V
R16: library part RES_33k_0603, "Thick Film Resistors - SMD 33 kOhms 100 mW 0603 5%", JLC=C4216, Manufacturer=YAGEO, Manufacturer Part Number=RC0603JR-0733KL, Tolerance=1%, Voltage Rating=50V
R17: library part RES_22k_0603, "Thick Film Resistors - SMD 22kOhms 1/10W 0603 1%", JLC=C31850, Manufacturer=YAGEO, Manufacturer Part Number=RC0603FR-7W22KL, Tolerance=1%, Voltage Rating=75V
R18 R19 R20 R21 R22 R23: library part RES_0R_0603, "Thick Film Resistors - SMD 1/10watt ZEROohm Jumper", JLC=C21189, Manufacturer=Vishay, Manufacturer Part Number=CRCW06030000Z0EA, Tolerance=1%, Voltage Rating=75V
R24: library part RES_DNF_0805, "Resistor SMD 0805 - not populated"
S1 S2 S3 S4 S5: library part SW_UK-B0228-G5-160-JZ, "No NO Gull Wing 50mA 6mm 100MΩ 100000 12V 160gf@±50gf -20℃~+70℃ 6mm 5mm Black Round Button Brick nogging SPST SMD Tactile Switches ROHS", JLC=C620316, Manufacturer=USAKRO
TP2 TP3: library part "MISC_Test Pad 0.7mm", "Test Pad surface mount", Manufacturer=N/A
VR1: library part IC_AP7375-33SA-7, "3.3V, 300mA LDO Spannungs-Regulator LDO High Voltage Standard SOT23 T&R 3K", JLC=C5944186, Manufacturer="Diodes Incorporated", Package=SOT-23
X1 X2: library part CON_HEADER_1X12_FEMALE_NO, "Board-to-Board-Steckverbinder, 2.54 mm, 12 Kontakt(e), Stiftleiste 1-Reihig", Manufacturer=WE, Manufacturer Part Number=61301211821
X3 X4 X5 X6 X7 X8 X9 X10 X11 X12 X13 X14 X15 X16 X17 X18 X19 X20 X21 X22 X23 X24 X27 X28 X29 X30 X31 X32 X35 X36 X37 X38 X39 X40 X48 X49 X50 X51 X52 X53 X54 X55 X56 X57 X58 X59 X60 X61 X62 X63 X64 X65: library part PAD_2.54
X25: library part CON_HEADER_1X2_FEMALE_NO, "Board-to-Board-Steckverbinder, 2.54 mm, 2 Kontakt(e), Stiftleiste 1-Reihig", Manufacturer=WE, Manufacturer Part Number=61300211821
X26 X33 X34: library part CON_HEADER_1X6_FEMALE_NO, "Board-to-Board-Steckverbinder, 2.54 mm, 6 Kontakt(e), Stiftleiste 1-Reihig", Manufacturer=WE, Manufacturer Part Number=61300611821
X41 X42 X43 X66: library part CON_HEADER_1X2, "Board-to-Board-Steckverbinder, 2.54 mm, 2 Kontakt(e), Stiftleiste 1-Reihig", Manufacturer=Samtec, Manufacturer Part Number=TSW-102-07-T-S
X44 X46: library part CON_MiniUSB-AB-SMT, "MicroUSB-B-SMT", Manufacturer="Amphenol ICC (FCI)"
X45: library part CON_2x5_SMD_1.27mm, "Pin Header 2x5, 1.27mm (50mil), SMD, Keying Shroud", Manufacturer=Samtec, Manufacturer Part Number=FTSH-105-01-L-DV-K
X47: library part CON_JST_B2B-XH, "Connector Header Through Hole 2 position 0.098\" (2.50mm)", JLC=C158012, Manufacturer=JST, Manufacturer Part Number="B2B-XH-A (LF)(SN)"

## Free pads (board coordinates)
  round 1.6 hole 1: 2(1.86,9.1) 2(1.86,11.64) 2(1.86,14.18) 2(1.86,16.72) 2(1.86,19.26) 2(1.86,21.8) 2(1.86,24.34) 2(1.86,26.88) 2(1.86,29.42) 2(1.86,31.96) 2(1.86,34.5) 2(1.86,37.04) 2(1.86,39.58) 2(1.86,42.12) 2(1.86,44.66) 2(1.86,47.2) 2(1.86,49.74) 2(1.86,52.28) 2(1.86,54.82) 2(1.86,57.36) 2(4.4,9.1) 2(4.4,11.64) 2(4.4,14.18) 2(4.4,16.72) 2(4.4,19.26) 2(4.4,21.8) 2(4.4,24.34) 2(4.4,26.88) 2(4.4,29.42) 2(4.4,31.96) 2(4.4,34.5) 2(4.4,37.04) 2(4.4,39.58) 2(4.4,42.12) 2(4.4,44.66) 2(4.4,47.2) 2(4.4,49.74) 2(4.4,52.28) 2(4.4,54.82) 2(4.4,57.36) 2(6.94,9.1) 2(6.94,11.64) 2(6.94,14.18) 2(6.94,16.72) 2(6.94,19.26) 2(6.94,21.8) 2(6.94,24.34) 2(6.94,26.88) 2(6.94,29.42) 2(6.94,31.96) 2(6.94,34.5) 2(6.94,37.04) 2(6.94,39.58) 2(6.94,42.12) 2(6.94,44.66) 2(6.94,47.2) 2(6.94,49.74) 2(6.94,52.28) 2(6.94,54.82) 2(6.94,57.36) 2(9.48,1.48) 2(9.48,4.02) 2(9.48,6.56) 2(9.48,9.1) 2(9.48,11.64) 2(9.48,14.18) 2(9.48,16.72) 2(9.48,19.26) 2(9.48,21.8) 2(9.48,24.34) 2(9.48,26.88) 2(9.48,29.42) 2(9.48,31.96) 2(9.48,34.5) 2(9.48,37.04) 2(9.48,39.58) 2(9.48,42.12) 2(9.48,44.66) 2(9.48,47.2) 2(9.48,49.74) 2(9.48,52.28) 2(9.48,54.82) 2(9.48,57.36) 2(9.48,59.9) 2(9.48,62.44) 2(9.48,64.98) 2(12.02,1.48) 2(12.02,4.02) 2(12.02,6.56) 2(12.02,9.1) 2(12.02,11.64) 2(12.02,14.18) 2(12.02,16.72) 2(12.02,19.26) 2(12.02,21.8) 2(12.02,24.34) 2(12.02,26.88) 2(12.02,29.42) 2(12.02,31.96) 2(12.02,34.5) 2(12.02,37.04) 2(12.02,39.58) 2(12.02,42.12) 2(12.02,44.66) 2(12.02,47.2) 2(12.02,49.74) 2(12.02,52.28) 2(12.02,54.82) 2(12.02,57.36) 2(12.02,59.9) 2(12.02,62.44) 2(12.02,64.98) 2(14.56,1.48) 2(14.56,4.02) 2(14.56,6.56) 2(14.56,9.1) 2(14.56,11.64) 2(14.56,14.18) 2(14.56,16.72) 2(14.56,19.26) 2(14.56,21.8) 2(14.56,24.34) 2(14.56,26.88) 2(14.56,29.42) 2(14.56,31.96) 2(14.56,34.5) 2(14.56,37.04) 2(14.56,39.58) 2(14.56,42.12) 2(14.56,44.66) 2(14.56,47.2) 2(14.56,49.74) 2(14.56,52.28) 2(14.56,54.82) 2(14.56,57.36) 2(14.56,59.9) 2(14.56,62.44) 2(14.56,64.98) 2(17.1,1.48) 2(17.1,4.02) 2(17.1,6.56) 2(17.1,9.1) 2(17.1,11.64) 2(17.1,14.18) 2(17.1,16.72) 2(17.1,19.26) 2(17.1,21.8) 2(17.1,24.34) 2(17.1,26.88) 2(17.1,29.42) 2(17.1,31.96) 2(17.1,34.5) 2(17.1,37.04) 2(17.1,39.58) 2(17.1,42.12) 2(17.1,44.66) 2(17.1,47.2) 2(17.1,49.74) 2(17.1,52.28) 2(17.1,54.82) 2(17.1,57.36) 2(17.1,59.9) 2(17.1,62.44) 2(17.1,64.98) 2(19.64,1.48) 2(19.64,4.02) 2(19.64,6.56) 2(19.64,9.1) 2(19.64,11.64) 2(19.64,14.18) 2(19.64,16.72) 2(19.64,19.26) 2(19.64,21.8) 2(19.64,24.34) 2(19.64,26.88) 2(19.64,29.42) 2(19.64,31.96) 2(19.64,34.5) 2(19.64,37.04) 2(19.64,39.58) 2(19.64,42.12) 2(19.64,44.66) 2(19.64,47.2) 2(19.64,49.74) 2(19.64,52.28) 2(19.64,54.82) 2(19.64,57.36) 2(19.64,59.9) 2(19.64,62.44) 2(19.64,64.98) 2(22.18,1.48) 2(22.18,4.02) 2(22.18,6.56) 2(22.18,9.1) 2(22.18,11.64) 2(22.18,14.18) 2(22.18,16.72) 2(22.18,19.26) 2(22.18,21.8) 2(22.18,24.34) 2(22.18,42.12) 2(22.18,44.66) 2(22.18,47.2) 2(22.18,49.74) 2(22.18,52.28) 2(22.18,54.82) 2(22.18,57.36) 2(22.18,59.9) 2(22.18,62.44) 2(22.18,64.98) 2(24.72,1.48) 2(24.72,4.02) 2(24.72,6.56) 2(24.72,9.1) 2(24.72,11.64) 2(24.72,14.18) 2(24.72,16.72) 2(24.72,19.26) 2(24.72,21.8) 2(24.72,24.34) 2(24.72,42.12) 2(24.72,44.66) 2(24.72,47.2) 2(24.72,49.74) 2(24.72,52.28) 2(24.72,54.82) 2(24.72,57.36) 2(24.72,59.9) 2(24.72,62.44) 2(24.72,64.98) 2(27.26,1.48) 2(27.26,4.02) 2(27.26,6.56) 2(27.26,9.1) 2(27.26,11.64) 2(27.26,14.18) 2(27.26,16.72) 2(27.26,21.8) 2(27.26,44.66) 2(27.26,47.2) 2(27.26,49.74) 2(27.26,52.28) 2(27.26,54.82) 2(27.26,57.36) 2(27.26,59.9) 2(27.26,62.44) 2(27.26,64.98) 2(29.8,1.48) 2(29.8,4.02) 2(29.8,6.56) 2(29.8,9.1) 2(29.8,11.64) 2(29.8,14.18) 2(29.8,16.72) 2(29.8,19.26) 2(29.8,49.74) 2(29.8,52.28) 2(29.8,54.82) 2(29.8,57.36) 2(29.8,59.9) 2(29.8,62.44) 2(29.8,64.98) 2(32.34,1.48) 2(32.34,4.02) 2(32.34,6.56) 2(32.34,9.1) 2(32.34,11.64) 2(32.34,14.18) 2(32.34,16.72) 2(32.34,19.26) 2(32.34,49.74) 2(32.34,52.28) 2(32.34,54.82) 2(32.34,57.36) 2(32.34,59.9) 2(32.34,62.44) 2(32.34,64.98) 2(34.88,1.48) 2(34.88,4.02) 2(34.88,6.56) 2(34.88,9.1) 2(34.88,11.64) 2(34.88,14.18) 2(34.88,16.72) 2(34.88,49.74) 2(34.88,52.28) 2(34.88,54.82) 2(34.88,57.36) 2(34.88,59.9) 2(34.88,62.44) 2(34.88,64.98) 2(37.42,1.48) 2(37.42,4.02) 2(37.42,6.56) 2(37.42,9.1) 2(37.42,11.64) 2(37.42,14.18) 2(37.42,16.72) 2(37.42,49.74) 2(37.42,52.28) 2(37.42,54.82) 2(37.42,57.36) 2(37.42,59.9) 2(37.42,62.44) 2(37.42,64.98) 2(39.96,1.48) 2(39.96,4.02) 2(39.96,6.56) 2(39.96,9.1) 2(39.96,11.64) 2(39.96,14.18) 2(39.96,16.72) 2(39.96,49.74) 2(39.96,52.28) 2(39.96,54.82) 2(39.96,57.36) 2(39.96,59.9) 2(39.96,62.44) 2(39.96,64.98) 2(42.5,1.48) 2(42.5,4.02) 2(42.5,6.56) 2(42.5,9.1) 2(42.5,11.64) 2(42.5,14.18) 2(42.5,16.72) 2(42.5,49.74) 2(42.5,52.28) 2(42.5,54.82) 2(42.5,57.36) 2(42.5,59.9) 2(42.5,62.44) 2(42.5,64.98) 2(45.04,1.48) 2(45.04,4.02) 2(45.04,6.56) 2(45.04,9.1) 2(45.04,11.64) 2(45.04,14.18) 2(45.04,16.72) 2(45.04,49.74) 2(45.04,52.28) 2(45.04,54.82) 2(45.04,57.36) 2(45.04,59.9) 2(45.04,62.44) 2(45.04,64.98) 2(47.58,1.48) 2(47.58,4.02) 2(47.58,6.56) 2(47.58,9.1) 2(47.58,11.64) 2(47.58,14.18) 2(47.58,16.72) 2(47.58,49.74) 2(47.58,52.28) 2(47.58,54.82) 2(47.58,57.36) 2(47.58,59.9) 2(47.58,62.44) 2(47.58,64.98) 2(50.12,1.48) 2(50.12,4.02) 2(50.12,6.56) 2(50.12,9.1) 2(50.12,11.64) 2(50.12,14.18) 2(50.12,16.72) 2(50.12,49.74) 2(50.12,52.28) 2(50.12,54.82) 2(50.12,57.36) 2(50.12,59.9) 2(50.12,62.44) 2(50.12,64.98) 2(52.66,1.48) 2(52.66,4.02) 2(52.66,6.56) 2(52.66,9.1) 2(52.66,11.64) 2(52.66,14.18) 2(52.66,16.72) 2(52.66,49.74) 2(52.66,52.28) 2(52.66,54.82) 2(52.66,57.36) 2(52.66,59.9) 2(52.66,62.44) 2(52.66,64.98) 2(55.2,1.48) 2(55.2,4.02) 2(55.2,6.56) 2(55.2,9.1) 2(55.2,11.64) 2(55.2,14.18) 2(55.2,16.72) 2(55.2,49.74) 2(55.2,52.28) 2(55.2,54.82) 2(55.2,57.36) 2(55.2,59.9) 2(55.2,62.44) 2(55.2,64.98) 2(57.74,1.48) 2(57.74,4.02) 2(57.74,6.56) 2(57.74,9.1) 2(57.74,11.64) 2(57.74,14.18) 2(57.74,16.72) 2(57.74,49.74) 2(57.74,52.28) 2(57.74,54.82) 2(57.74,57.36) 2(57.74,59.9) 2(57.74,62.44) 2(57.74,64.98)
  round 2 hole 2.6 unplated: 6(4,4) 6(4,63) 6(96,4) 6(96,63)

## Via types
v1: diameter 0.6, hole 0.3, Top Layer to Bottom Layer, 81 vias

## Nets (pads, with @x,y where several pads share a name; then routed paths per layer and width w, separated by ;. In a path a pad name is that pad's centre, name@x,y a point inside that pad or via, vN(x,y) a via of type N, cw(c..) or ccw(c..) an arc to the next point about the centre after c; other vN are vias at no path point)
3V3: C6.1 C9.1 L1.1 R1.2 R2.2 R8.2 R10.1 R14.2 VR1.2 X33.5 X41.1 X42.1 X45.1 X49.1 X50.1 X51.1 | length 24
  Top Layer w0.2: R1.2@68.8,3.2 v1(68.8,4.3) ; v1(75.19,4.369) 75.19,4.297 75.675,3.812 75.675,3.81 76.05,3.435 R2.2@76.05,3.2 ; R8.2@83.05,3.1 v1(83.05,4.2) ; v1(89.458,4.181) 89.951,3.688 89.976,3.688 90.35,3.315 R14.2@90.35,3.1 ; X45.1@96.95,50.565 v1@98.89,50.565
  Top Layer w0.5: R10.1@97.4,44.7 v1(98.2,44.7)
  Top Layer w0.8: C6.1@92.89,44.64 v1(92.89,46.153) v1@92.89,46.99 ; VR1.2@92.9,42.969 C6.1@92.9,44.55
  Top Layer w1: X41.1@72.44,57.1 72.6,57.26 72.6,61.8 L1.1@72.8,62 72.8,62.4 73.05,62.65 C9.1@77,62.65 ; C9.1@76.8,62.7 v1(79.15,62.7)
  other v1: 92.9,47 98.913,50.588
3V3A: C10.1 L1.2 R6.3 R13.3 X33.4 X41.2 X48.1 | length 75.8
  Top Layer w1: C10.1@65.1,62.75 68.95,62.75 69.2,62.5 L1.2@69.2,62 69.2,57.962 69.9,57.262 X41.2@69.9,57.1
  Mid-Layer 2 w1: X33.4@57.74,34.5 X33.4@57.84,34.5 67,34.5 R13.3@71,38.5 ; X48.1@60.539,64.939 68.761,64.939 69.9,63.8 X41.2@69.9,57.1 70.015,56.985 70.015,42.285 71,41.3 R13.3@71,38.5 ; R6.3@85,38.5 83.3,36.8 72.7,36.8 R13.3@71,38.5
5V0: C5.1 D8.2 D9.2 D10.2 R24.1 VR1.1 | length 40.9
  Top Layer w0.6: VR1.1@92.9,40.85 93.5,40.85 93.75,40.85 95.425,42.525 96.242,41.708 97.383,40.567 98.192,40.567 99.075,39.684 99.075,30.7 98.875,30.5 D9.2@98.775,30.5 ; D8.2@93.175,38.6 VR1.1@93.175,40.85 ; D9.2@98.7,30.294 D9.2@98.7,30.5
  Top Layer w0.8: R24.1@82.9,56.775 82.975,56.7 83.2,56.7 83.475,56.425 D10.2@83.475,55 84.275,54.2 86.525,51.95 89.67,48.805 93.011,48.805 94.35,47.466 94.35,45.572 94.35,43.707 C5.1@95.166,42.891
Analog_In_0: R20.2 X2.1 X24.1 | length 27.7
  Top Layer w0.2: X2.1@57.74,42.12 X24.1@57.74,47.2
  Top Layer w0.3: X2.1@57.74,42.12 75.08,42.12 76.8,40.4 R20.2@76.8,37.55
Analog_In_1: R21.2 X2.2 X23.1 | length 22.3
  Top Layer w0.2: X2.2@55.2,42.12 X23.1@55.2,47.2
  Top Layer w0.3: X2.2@55.2,42.12 56.504,40.816 66.684,40.816 67.1,40.4 v1(67.1,36.6) R21.2@66.3,36.6
Analog_In_2: X2.3 X22.1 | length 5.1
  Top Layer w0.2: X2.3@52.66,42.12 X22.1@52.66,47.2
Analog_In_3: X2.4 X20.1 | length 5.1
  Top Layer w0.2: X2.4@50.12,42.12 X20.1@50.12,47.2
Boot_0: X33.6 X42.2 | length 32.4
  Mid-Layer 2 w0.2: X33.6@57.74,39.58 56.52,40.8 54.6,40.8 53.8,40 53.8,32.5 55.532,30.768 70.568,30.768 70.8,31 X42.2@73.1,31
CTS_CP2102: IC1.15 TP2.1 | length 3.6
  Top Layer w0.2: TP2.1@77.404,24.096 TP2.1@77.5,24 ; TP2.1@77.817,24 80.2,24 IC1.15@81,24.8
DBG_USB_N: D7.1 D7.10 IC1.5 X46.2 | length 18.2
  Top Layer w0.14: IC1.5@84.13,26.27 84.23,26.17 84.519,26.17 84.565,26.124 85.34,26.124 86.753,24.71 89.662,24.71 91.142,26.19 91.695,26.19 91.905,26.4 93.095,26.4 93.125,26.37 93.185,26.37 93.201,26.354 93.317,26.354 93.43,26.467 93.43,26.772 94.068,27.41 96.518,27.41 96.77,27.158 96.77,25.26 96.44,24.93 95.58,24.93 X46.2@95.4,24.75
DBG_USB_P: D7.2 D7.9 IC1.4 X46.3 | length 18.1
  Top Layer w0.14: IC1.4@84.05,25.75 84.13,25.83 84.579,25.83 84.583,25.834 85.22,25.834 86.633,24.42 89.782,24.42 91.262,25.9 91.695,25.9 D7.2@92.085,25.9 92.735,25.9 92.765,25.93 93.241,25.93 93.375,26.064 93.437,26.064 93.72,26.347 93.72,26.652 94.188,27.12 96.398,27.12 96.48,27.038 96.48,26.8 96.48,26.49 cw(c96.34,26.49) 96.34,26.35 96.3,26.35 ccw(c96.3,26.23) 96.3,26.11 96.34,26.11 cw(c96.34,25.97) 96.48,25.97 96.48,25.51 96.48,25.38 96.32,25.22 95.58,25.22 95.4,25.4 X46.3@94.925,25.4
